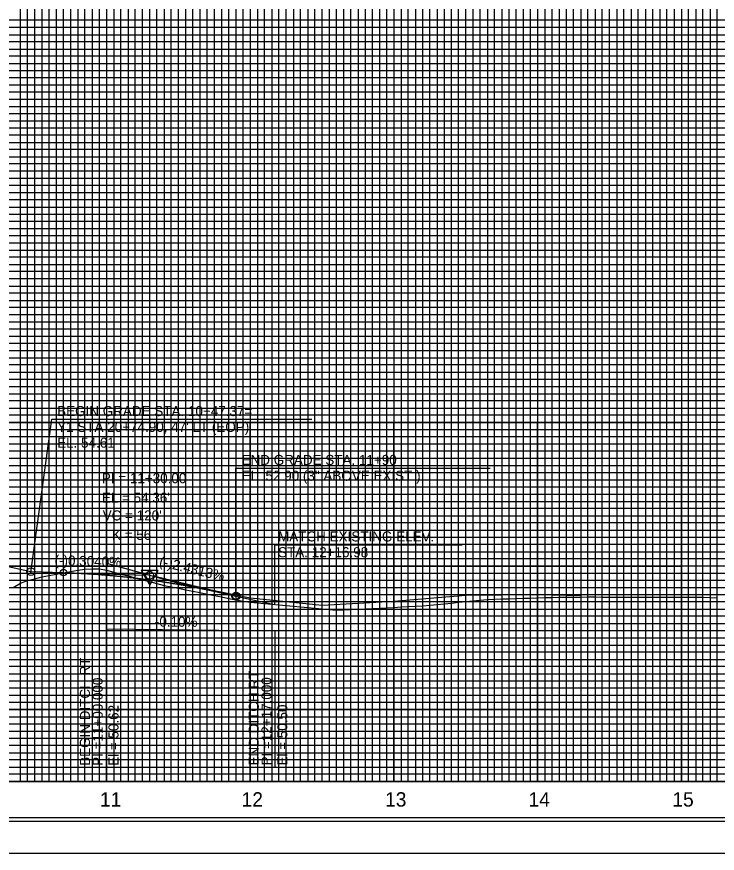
# Model space of a CAD drawing. Extents: x 2345490 to 2445302, y 465165 to 573888.
# Drawn here: x 2381804 to 2382292, y 532361 to 532944 of the extents above; entities that cross this region are included whole.
import ezdxf

# ---------------------------------------------------------------- set-up
doc = ezdxf.new("R2010")
doc.units = 0
for name, color, linetype in [('Old_Level_1', 7, 'Continuous'), ('Old_Level_18', 7, 'Continuous'), ('Old_Level_2', 7, 'Continuous'), ('Old_Level_3', 7, 'Continuous'), ('Old_Level_41', 7, 'Continuous'), ('Old_Level_42', 7, 'Continuous'), ('Old_Level_43', 7, 'Continuous'), ('Old_Level_50', 7, 'Continuous'), ('Old_Level_51', 7, 'Continuous'), ('Old_Level_57', 7, 'Continuous'), ('Old_Level_62', 7, 'Continuous'), ('Old_Level_63', 7, 'Continuous')]:
    doc.layers.add(name, color=color, linetype=linetype)

msp = doc.modelspace()

# ---------------------------------------------------------------- linework, layer by layer
at = {"layer": 'Old_Level_1'}
for points in [[(2381801.799, 532546.145), (2381806.799, 532549.13275), (2381811.799, 532550.8695), (2381816.799, 532552.128), (2381821.799, 532553.4715), (2381826.799, 532554.3915), (2381831.799, 532555.2835), (2381836.799, 532556.27575), (2381841.799, 532557.2585), (2381846.799, 532558.14025), (2381851.799, 532558.90725), (2381856.799, 532559.102), (2381861.799, 532559.02975), (2381866.799, 532558.10175), (2381871.799, 532556.787), (2381876.799, 532555.472), (2381881.799, 532554.15725), (2381886.799, 532552.84225), (2381891.799, 532551.5275), (2381896.799, 532550.2095), (2381901.799, 532548.89425), (2381906.799, 532547.6065), (2381911.799, 532546.603), (2381916.799, 532545.59575), (2381921.799, 532544.58425), (2381926.799, 532543.57275), (2381931.799, 532542.5615), (2381936.799, 532541.56275), (2381941.799, 532540.554), (2381946.799, 532539.54525), (2381951.799, 532538.5365), (2381956.799, 532537.528), (2381961.799, 532536.51925), (2381966.799, 532535.87925), (2381971.799, 532535.4215), (2381976.799, 532534.964), (2381981.799, 532534.5065), (2381986.799, 532534.04875), (2381991.799, 532533.59125), (2381996.799, 532533.121), (2382001.799, 532532.6625), (2382006.799, 532532.20425), (2382011.799, 532531.74575), (2382016.799, 532531.28725), (2382021.799, 532530.82875), (2382026.799, 532530.425), (2382031.799, 532530.49175), (2382036.799, 532530.76025), (2382041.799, 532531.0285), (2382046.799, 532531.29675), (2382051.799, 532531.56525), (2382056.799, 532531.8335), (2382061.799, 532532.00825), (2382066.799, 532532.2765), (2382071.799, 532532.54475), (2382076.799, 532532.81325), (2382081.799, 532533.0815), (2382086.799, 532533.35), (2382091.799, 532533.7715), (2382096.799, 532534.27475), (2382101.799, 532534.778), (2382106.799, 532535.28125), (2382111.799, 532535.78425), (2382116.799, 532536.2875), (2382121.799, 532536.79075), (2382126.799, 532537.294), (2382131.799, 532537.76775), (2382136.799, 532537.97175), (2382141.799, 532538.1305), (2382146.799, 532538.28925), (2382151.799, 532538.448), (2382156.799, 532538.61975), (2382161.799, 532538.778), (2382166.799, 532538.93525), (2382171.799, 532539.089), (2382176.799, 532539.2225), (2382181.799, 532539.289), (2382186.799, 532539.35175), (2382191.799, 532539.41125), (2382196.799, 532539.467), (2382201.799, 532539.50625), (2382206.799, 532539.50325), (2382211.799, 532539.495), (2382216.799, 532539.48275), (2382221.799, 532539.467), (2382226.799, 532539.44825), (2382231.799, 532539.45125), (2382236.799, 532539.46675), (2382241.799, 532539.47825), (2382246.799, 532539.48625), (2382251.799, 532539.4905), (2382256.799, 532539.415), (2382261.799, 532539.396), (2382266.799, 532539.393)], [(2382266.799, 532539.393), (2382271.799, 532539.3855), (2382276.799, 532539.37325), (2382281.799, 532539.31625), (2382286.799, 532539.1095), (2382291.799, 532538.9875)]]:
    msp.add_lwpolyline(points, dxfattribs=at)
at = {"layer": 'Old_Level_18'}
msp.add_lwpolyline([(2383216.79875, 533436.04975), (2381716.79875, 533436.04975), (2381716.79875, 532386.04975), (2383216.79875, 532386.04975)], close=True, dxfattribs=at)
at = {"layer": 'Old_Level_2'}
for p, q in [((2381791.799, 532562.18325), (2381814.16925, 532557.15)), ((2381814.16925, 532557.15), (2381836.799, 532556.46225)), ((2381836.799, 532556.46225), (2381894.0505, 532554.72175)), ((2381956.799, 532540.05), (2381899.47125, 532553.9885)), ((2381956.799, 532540.05), (2381983.779, 532534.35025))]:
    msp.add_line(p, q, dxfattribs=at)
msp.add_lwpolyline([(2381902.72475, 532557.9225), (2381890.98225, 532557.908), (2381896.86575, 532547.78975)], close=True, dxfattribs=at)
for centre, radius in [((2381814.16925, 532557.15), 2.75), ((2381836.799, 532556.46225), 2.25), ((2381896.799, 532554.638), 2.75), ((2381896.799, 532554.638), 2.75), ((2381956.799, 532540.05), 2.75), ((2381956.799, 532540.05), 2.25)]:
    msp.add_circle(centre, radius, dxfattribs=at)
msp.add_spline([(2381836.799, 532556.46225), (2381839.199, 532556.384), (2381841.599, 532556.29575), (2381843.999, 532556.19725), (2381846.399, 532556.0885), (2381848.799, 532555.96975), (2381851.199, 532555.8405), (2381853.599, 532555.70125), (2381855.999, 532555.55175), (2381858.399, 532555.392), (2381860.799, 532555.222), (2381863.199, 532555.04175), (2381865.599, 532554.8515), (2381867.999, 532554.65075), (2381870.399, 532554.44), (2381872.799, 532554.219), (2381875.199, 532553.98775), (2381877.599, 532553.74625), (2381879.999, 532553.49475), (2381882.399, 532553.23275), (2381884.799, 532552.96075), (2381887.199, 532552.6785), (2381889.599, 532552.386), (2381891.999, 532552.08325), (2381894.399, 532551.77025), (2381896.799, 532551.447), (2381899.199, 532551.11375), (2381901.599, 532550.77025), (2381903.999, 532550.4165), (2381906.399, 532550.0525), (2381908.799, 532549.67825), (2381911.199, 532549.29375), (2381913.599, 532548.89925), (2381915.999, 532548.4945), (2381918.399, 532548.0795), (2381920.799, 532547.65425), (2381923.199, 532547.21875), (2381925.599, 532546.773), (2381927.999, 532546.31725), (2381930.399, 532545.851), (2381932.799, 532545.37475), (2381935.199, 532544.88825), (2381937.599, 532544.3915), (2381939.999, 532543.8845), (2381942.399, 532543.3675), (2381944.799, 532542.84), (2381947.199, 532542.3025), (2381949.599, 532541.75475), (2381951.999, 532541.19675), (2381954.399, 532540.6285), (2381956.799, 532540.05)], degree=3, dxfattribs=at)
at = {"layer": 'Old_Level_3'}
for p, q in [((2381814.03875, 532556.54975), (2381828.82525, 532663.237)), ((2381828.82525, 532663.237), (2382009.71375, 532663.237)), ((2381956.799, 532540.05), (2381956.799, 532629.18325)), ((2381956.799, 532629.18325), (2382133.76675, 532629.18325)), ((2381983.77875, 532575.91425), (2381983.77875, 532534.35025)), ((2381983.77875, 532575.91425), (2382114.25025, 532575.91425)), ((2381866.799, 532517.25), (2381983.799, 532516.05)), ((2381866.799, 532517.25), (2381866.799, 532420.84507)), ((2381983.799, 532516.05), (2381983.799, 532420.84507))]:
    msp.add_line(p, q, dxfattribs=at)
at = {"layer": 'Old_Level_41'}
msp.add_line((2383216.79875, 532411.04975), (2381716.79875, 532411.04975), dxfattribs=at)
for points in [[(2381716.79875, 533436.04975), (2381766.79875, 533436.04975), (2381766.79875, 532411.04975), (2381816.79875, 532411.04975), (2381816.79875, 533436.04975), (2381866.79875, 533436.04975), (2381866.79875, 532411.04975), (2381916.79875, 532411.04975), (2381916.79875, 533436.04975), (2381966.79875, 533436.04975), (2381966.79875, 532411.04975), (2382016.79875, 532411.04975), (2382016.79875, 533436.04975), (2382066.79875, 533436.04975), (2382066.79875, 532411.04975), (2382116.79875, 532411.04975), (2382116.79875, 533436.04975), (2382166.79875, 533436.04975), (2382166.79875, 532411.04975), (2382216.79875, 532411.04975), (2382216.79875, 533436.04975), (2382266.79875, 533436.04975), (2382266.79875, 532411.04975), (2382316.79875, 532411.04975)], [(2381791.79875, 532411.04975), (2381791.79875, 533436.04975), (2381841.79875, 533436.04975), (2381841.79875, 532411.04975), (2381891.79875, 532411.04975), (2381891.79875, 533436.04975), (2381941.79875, 533436.04975), (2381941.79875, 532411.04975), (2381991.79875, 532411.04975), (2381991.79875, 533436.04975), (2382041.79875, 533436.04975), (2382041.79875, 532411.04975), (2382091.79875, 532411.04975), (2382091.79875, 533436.04975), (2382141.79875, 533436.04975), (2382141.79875, 532411.04975), (2382191.79875, 532411.04975), (2382191.79875, 533436.04975), (2382241.79875, 533436.04975), (2382241.79875, 532411.04975), (2382291.79875, 532411.04975), (2382291.79875, 533436.04975), (2382341.79875, 533436.04975)], [(2383216.79875, 532936.04975), (2381716.79875, 532936.04975), (2381716.79875, 532886.04975), (2383216.79875, 532886.04975)], [(2383216.79875, 532836.04975), (2381716.79875, 532836.04975), (2381716.79875, 532786.04975), (2383216.79875, 532786.04975)], [(2383216.79875, 532761.04975), (2381716.79875, 532761.04975), (2381716.79875, 532811.04975), (2383216.79875, 532811.04975)], [(2383216.79875, 532736.04975), (2381716.79875, 532736.04975), (2381716.79875, 532686.04975), (2383216.79875, 532686.04975)], [(2383216.79875, 532661.04975), (2381716.79875, 532661.04975), (2381716.79875, 532711.04975), (2383216.79875, 532711.04975)], [(2383216.79875, 532636.04975), (2381716.79875, 532636.04975), (2381716.79875, 532586.04975), (2383216.79875, 532586.04975)], [(2383216.79875, 532536.04975), (2381716.79875, 532536.04975), (2381716.79875, 532486.04975), (2383216.79875, 532486.04975)], [(2383216.79875, 532461.04975), (2381716.79875, 532461.04975), (2381716.79875, 532511.04975), (2383216.79875, 532511.04975)], [(2383216.79875, 532436.04975), (2381716.79875, 532436.04975)]]:
    msp.add_lwpolyline(points, dxfattribs=at)
at = {"layer": 'Old_Level_42'}
for points in [[(2383216.79875, 532861.04975), (2381716.79875, 532861.04975), (2381716.79875, 532911.04975), (2383216.79875, 532911.04975)], [(2383216.79875, 532561.04975), (2381716.79875, 532561.04975), (2381716.79875, 532611.04975), (2383216.79875, 532611.04975)]]:
    msp.add_lwpolyline(points, dxfattribs=at)
at = {"layer": 'Old_Level_43'}
for points in [[(2381806.79875, 533436.04975), (2381806.79875, 532411.04975), (2381811.79875, 532411.04975), (2381811.79875, 533436.04975)], [(2381821.79875, 533436.04975), (2381821.79875, 532411.04975), (2381826.79875, 532411.04975), (2381826.79875, 533436.04975)], [(2381831.79875, 533436.04975), (2381831.79875, 532411.04975), (2381836.79875, 532411.04975), (2381836.79875, 533436.04975)], [(2381846.79875, 533436.04975), (2381846.79875, 532411.04975), (2381851.79875, 532411.04975), (2381851.79875, 533436.04975)], [(2381856.79875, 533436.04975), (2381856.79875, 532411.04975), (2381861.79875, 532411.04975), (2381861.79875, 533436.04975)], [(2381871.79875, 533436.04975), (2381871.79875, 532411.04975), (2381876.79875, 532411.04975), (2381876.79875, 533436.04975)], [(2381881.79875, 533436.04975), (2381881.79875, 532411.04975), (2381886.79875, 532411.04975), (2381886.79875, 533436.04975)], [(2381896.79875, 533436.04975), (2381896.79875, 532411.04975), (2381901.79875, 532411.04975), (2381901.79875, 533436.04975)], [(2381906.79875, 533436.04975), (2381906.79875, 532411.04975), (2381911.79875, 532411.04975), (2381911.79875, 533436.04975)], [(2381921.79875, 533436.04975), (2381921.79875, 532411.04975), (2381926.79875, 532411.04975), (2381926.79875, 533436.04975)], [(2381931.79875, 532411.04975), (2381936.79875, 532411.04975), (2381936.79875, 533436.04975)], [(2381931.79875, 533436.04975), (2381931.79875, 532411.04975)], [(2381946.79875, 533436.04975), (2381946.79875, 532411.04975), (2381951.79875, 532411.04975), (2381951.79875, 533436.04975)], [(2381956.79875, 533436.04975), (2381956.79875, 532411.04975), (2381961.79875, 532411.04975), (2381961.79875, 533436.04975)], [(2381971.79875, 533436.04975), (2381971.79875, 532411.04975), (2381976.79875, 532411.04975), (2381976.79875, 533436.04975)], [(2381981.79875, 533436.04975), (2381981.79875, 532411.04975), (2381986.79875, 532411.04975), (2381986.79875, 533436.04975)], [(2381996.79875, 533436.04975), (2381996.79875, 532411.04975), (2382001.79875, 532411.04975), (2382001.79875, 533436.04975)], [(2382006.79875, 533436.04975), (2382006.79875, 532411.04975), (2382011.79875, 532411.04975), (2382011.79875, 533436.04975)], [(2382021.79875, 533436.04975), (2382021.79875, 532411.04975), (2382026.79875, 532411.04975), (2382026.79875, 533436.04975)], [(2382031.79875, 533436.04975), (2382031.79875, 532411.04975), (2382036.79875, 532411.04975), (2382036.79875, 533436.04975)], [(2382046.79875, 533436.04975), (2382046.79875, 532411.04975), (2382051.79875, 532411.04975), (2382051.79875, 533436.04975)], [(2382056.79875, 533436.04975), (2382056.79875, 532411.04975), (2382061.79875, 532411.04975), (2382061.79875, 533436.04975)], [(2382071.79875, 533436.04975), (2382071.79875, 532411.04975), (2382076.79875, 532411.04975), (2382076.79875, 533436.04975)], [(2382081.79875, 533436.04975), (2382081.79875, 532411.04975), (2382086.79875, 532411.04975), (2382086.79875, 533436.04975)], [(2382096.79875, 533436.04975), (2382096.79875, 532411.04975), (2382111.79875, 532411.04975), (2382111.79875, 533436.04975)], [(2382101.79875, 533436.04975), (2382101.79875, 532411.04975), (2382106.79875, 532411.04975), (2382106.79875, 533436.04975)], [(2382121.79875, 533436.04975), (2382121.79875, 532411.04975), (2382126.79875, 532411.04975), (2382126.79875, 533436.04975)], [(2382131.79875, 533436.04975), (2382131.79875, 532411.04975), (2382136.79875, 532411.04975), (2382136.79875, 533436.04975)], [(2382146.79875, 533436.04975), (2382146.79875, 532411.04975), (2382151.79875, 532411.04975), (2382151.79875, 533436.04975)], [(2382156.79875, 533436.04975), (2382156.79875, 532411.04975), (2382161.79875, 532411.04975), (2382161.79875, 533436.04975)], [(2382171.79875, 533436.04975), (2382171.79875, 532411.04975), (2382176.79875, 532411.04975), (2382176.79875, 533436.04975)], [(2382181.79875, 533436.04975), (2382181.79875, 532411.04975), (2382186.79875, 532411.04975), (2382186.79875, 533436.04975)], [(2382196.79875, 533436.04975), (2382196.79875, 532411.04975), (2382201.79875, 532411.04975), (2382201.79875, 533436.04975)], [(2382206.79875, 533436.04975), (2382206.79875, 532411.04975), (2382211.79875, 532411.04975), (2382211.79875, 533436.04975)], [(2382221.79875, 533436.04975), (2382221.79875, 532411.04975), (2382226.79875, 532411.04975), (2382226.79875, 533436.04975)], [(2382231.79875, 533436.04975), (2382231.79875, 532411.04975), (2382236.79875, 532411.04975), (2382236.79875, 533436.04975)], [(2382246.79875, 533436.04975), (2382246.79875, 532411.04975)], [(2382251.79875, 533436.04975), (2382251.79875, 532411.04975), (2382256.79875, 532411.04975), (2382256.79875, 533436.04975), (2382261.79875, 533436.04975), (2382261.79875, 532411.04975), (2382271.79875, 532411.04975), (2382271.79875, 533436.04975), (2382276.79875, 533436.04975), (2382276.79875, 532411.04975), (2382281.79875, 532411.04975), (2382281.79875, 533436.04975), (2382286.79875, 533436.04975), (2382286.79875, 532411.04975)], [(2382101.79875, 533435.44975), (2382101.79875, 532411.04975), (2382106.79875, 532411.04975), (2382106.79875, 533435.44975)], [(2383166.79875, 532941.04975), (2381766.79875, 532941.04975), (2381766.79875, 532931.04975), (2383166.79875, 532931.04975)], [(2383166.79875, 532926.04975), (2381766.79875, 532926.04975), (2381766.79875, 532921.04975), (2383166.79875, 532921.04975)], [(2383166.79875, 532916.04975), (2381766.79875, 532916.04975)], [(2381766.79875, 532906.04975), (2383166.79875, 532906.04975)], [(2383166.79875, 532901.04975), (2381766.79875, 532901.04975), (2381766.79875, 532896.04975), (2383166.79875, 532896.04975)], [(2383166.79875, 532891.04975), (2381766.79875, 532891.04975), (2381766.79875, 532881.04975), (2383166.79875, 532881.04975)], [(2383166.79875, 532876.04975), (2381766.79875, 532876.04975), (2381766.79875, 532871.04975), (2383166.79875, 532871.04975)], [(2383166.79875, 532866.04975), (2381766.79875, 532866.04975), (2381766.79875, 532856.04975), (2383166.79875, 532856.04975)], [(2383166.79875, 532851.04975), (2381766.79875, 532851.04975), (2381766.79875, 532846.04975), (2383166.79875, 532846.04975)], [(2383166.79875, 532841.04975), (2381766.79875, 532841.04975), (2381766.79875, 532831.04975), (2383166.79875, 532831.04975)], [(2383166.79875, 532826.04975), (2381766.79875, 532826.04975), (2381766.79875, 532821.04975), (2383166.79875, 532821.04975)], [(2383166.79875, 532816.04975), (2381766.79875, 532816.04975), (2381766.79875, 532806.04975), (2383166.79875, 532806.04975)], [(2383166.79875, 532801.04975), (2381766.79875, 532801.04975), (2381766.79875, 532796.04975), (2383166.79875, 532796.04975)], [(2383166.79875, 532791.04975), (2381766.79875, 532791.04975), (2381766.79875, 532781.04975), (2383166.79875, 532781.04975)], [(2383166.79875, 532776.04975), (2381766.79875, 532776.04975), (2381766.79875, 532771.04975), (2383166.79875, 532771.04975)], [(2383166.79875, 532766.04975), (2381766.79875, 532766.04975), (2381766.79875, 532756.04975), (2383166.79875, 532756.04975)], [(2383166.79875, 532751.04975), (2381766.79875, 532751.04975), (2381766.79875, 532746.04975), (2383166.79875, 532746.04975)], [(2383166.79875, 532741.04975), (2381766.79875, 532741.04975), (2381766.79875, 532731.04975), (2383166.79875, 532731.04975)], [(2383166.79875, 532726.04975), (2381766.79875, 532726.04975), (2381766.79875, 532721.04975), (2383166.79875, 532721.04975)], [(2383166.79875, 532716.04975), (2381766.79875, 532716.04975), (2381766.79875, 532706.04975), (2383166.79875, 532706.04975)], [(2383166.79875, 532701.04975), (2381766.79875, 532701.04975), (2381766.79875, 532696.04975), (2383166.79875, 532696.04975)], [(2383166.79875, 532691.04975), (2381766.79875, 532691.04975), (2381766.79875, 532681.04975), (2383166.79875, 532681.04975)], [(2383166.79875, 532676.04975), (2381766.79875, 532676.04975), (2381766.79875, 532671.04975), (2383166.79875, 532671.04975)], [(2383166.79875, 532666.04975), (2381766.79875, 532666.04975), (2381766.79875, 532656.04975), (2383166.79875, 532656.04975)], [(2383166.79875, 532651.04975), (2381766.79875, 532651.04975), (2381766.79875, 532646.04975), (2383166.79875, 532646.04975)], [(2383166.79875, 532641.04975), (2381766.79875, 532641.04975), (2381766.79875, 532631.04975), (2383166.79875, 532631.04975)], [(2383166.79875, 532626.04975), (2381766.79875, 532626.04975), (2381766.79875, 532621.04975), (2383166.79875, 532621.04975)], [(2383166.79875, 532616.04975), (2381766.79875, 532616.04975)], [(2381766.79875, 532606.04975), (2383166.79875, 532606.04975)], [(2383166.79875, 532601.04975), (2381766.79875, 532601.04975), (2381766.79875, 532596.04975), (2383166.79875, 532596.04975)], [(2383166.79875, 532591.04975), (2381766.79875, 532591.04975)], [(2381766.79875, 532581.04975), (2383166.79875, 532581.04975)], [(2383166.79875, 532576.04975), (2381766.79875, 532576.04975), (2381766.79875, 532571.04975), (2383166.79875, 532571.04975)], [(2383166.79875, 532566.04975), (2381766.79875, 532566.04975), (2381766.79875, 532556.04975), (2383166.79875, 532556.04975)], [(2383166.79875, 532551.04975), (2381766.79875, 532551.04975), (2381766.79875, 532546.04975), (2383166.79875, 532546.04975)], [(2383166.79875, 532541.04975), (2381766.79875, 532541.04975), (2381766.79875, 532531.04975), (2383166.79875, 532531.04975)], [(2383166.79875, 532526.04975), (2381766.79875, 532526.04975), (2381766.79875, 532521.04975), (2383166.79875, 532521.04975)], [(2383166.79875, 532516.04975), (2381766.79875, 532516.04975), (2381766.79875, 532506.04975), (2383166.79875, 532506.04975)], [(2383166.79875, 532501.04975), (2381766.79875, 532501.04975), (2381766.79875, 532496.04975), (2383166.79875, 532496.04975)], [(2383166.79875, 532491.04975), (2381766.79875, 532491.04975), (2381766.79875, 532481.04975), (2383166.79875, 532481.04975)], [(2383166.79875, 532476.04975), (2381766.79875, 532476.04975), (2381766.79875, 532471.04975), (2383166.79875, 532471.04975)], [(2383166.79875, 532466.04975), (2381766.79875, 532466.04975), (2381766.79875, 532456.04975), (2383166.79875, 532456.04975)], [(2383166.79875, 532451.04975), (2381766.79875, 532451.04975), (2381766.79875, 532446.04975), (2383166.79875, 532446.04975)], [(2383166.79875, 532441.04975), (2381766.79875, 532441.04975), (2381766.79875, 532431.04975), (2383166.79875, 532431.04975)], [(2383166.79875, 532426.04975), (2381766.79875, 532426.04975), (2381766.79875, 532421.04975), (2383166.79875, 532421.04975)], [(2383166.79875, 532416.04975), (2381766.79875, 532416.04975)]]:
    msp.add_lwpolyline(points, dxfattribs=at)
at = {"layer": 'Old_Level_50'}
msp.add_lwpolyline([(2383229.29875, 533438.59975), (2381562.79875, 533438.59975), (2381562.79875, 532383.49975), (2383229.29875, 532383.49975)], close=True, dxfattribs=at)
at = {"layer": 'Old_Level_51'}
msp.add_lwpolyline([(2383233.79875, 533461.04975), (2381549.79875, 533461.04975), (2381549.79875, 532361.04975), (2383233.79875, 532361.04975)], close=True, dxfattribs=at)
at = {"layer": 'Old_Level_57'}
for p, q in [((2381716.79925, 532661.05025), (2382266.79875, 532661.05025)), ((2381866.79875, 532411.05025), (2381866.79875, 532661.05025)), ((2381966.79875, 532411.05025), (2381966.79875, 532661.05025)), ((2382066.79875, 532411.05025), (2382066.79875, 532661.05025)), ((2382166.79875, 532411.05025), (2382166.79875, 532661.05025)), ((2382266.79875, 532411.05025), (2382266.79875, 532661.05025)), ((2381716.79925, 532611.05025), (2382266.79875, 532611.05025)), ((2381716.79925, 532561.05025), (2382266.79875, 532561.05025)), ((2381716.79925, 532511.05025), (2382266.79875, 532511.05025)), ((2381716.799, 532461.05025), (2382266.79875, 532461.05025)), ((2381716.79925, 532411.05025), (2382266.79875, 532411.05025))]:
    msp.add_line(p, q, dxfattribs=at)
at = {"layer": 'Old_Level_63'}
msp.add_line((2381766.79875, 532411.04975), (2382198.83425, 532411.04975), dxfattribs=at)
msp.add_lwpolyline([(2381866.799, 532563.05), (2381916.799, 532549.05), (2381966.799, 532538.95), (2382016.799, 532533.85), (2382066.799, 532536.65), (2382116.799, 532540.85), (2382166.799, 532541.35), (2382196.799, 532540.55)], dxfattribs=at)

# ---------------------------------------------------------------- texts
at = {"layer": 'Old_Level_2'}
for s, height, p in [('BEGIN GRADE STA. 10+47.37=', 7.0000005, (2381832.41675, 532665.46)), ("Y1 STA 20+74.90, 47' LT (EOP)", 7.0000005, (2381832.41675, 532654.46)), ('EL. 54.61', 7.000001, (2381832.41675, 532643.46)), ('END GRADE STA. 11+90', 7.0000005, (2381960.788, 532631.4475)), ('EL. 52.90 (3" ABOVE EXIST.)', 7.0000005, (2381960.788, 532620.4475)), ('PI = 11+30.00', 7.0000005, (2381863.519, 532618.7195)), ("EL = 54.36'", 7.0000005, (2381863.5195, 532605.171)), ("VC = 120'", 7.000001, (2381864.124, 532592.79775)), ('K = 56', 7.000001, (2381870.573, 532579.2735)), ('MATCH EXISTING ELEV.', 7.0000005, (2381986.16675, 532578.17825)), ('STA. 12+16.98', 7.0000005, (2381986.16675, 532567.17825))]:
    msp.add_text(s, height=height, dxfattribs=at).set_placement(p)
for s, rotation, p in [('(-)0.3040%', 358.25869167, (2381830.54325, 532561.69675)), ('(-)2.4313%', 346.33466389, (2381902.9915, 532561.28375))]:
    msp.add_text(s, height=7.000001, rotation=rotation, dxfattribs=at).set_placement(p)
at = {"layer": 'Old_Level_3'}
for s, height, rotation, p in [('-0.10%', 7, 359.4124, (2381900.3665, 532518.971)), ('BEGIN DITCH RT', 7.0000005, 90, (2381855.24905, 532421.93915)), ('END DITCH RT', 7.0000005, 90, (2381972.75967, 532422.18661)), ('PI =11+00.000', 7.0000005, 90, (2381864.12295, 532421.93915)), ('PI =12+17.000', 7.0000005, 90, (2381981.63358, 532422.18661)), ('El = 50.62', 7.000001, 90, (2381875.12295, 532421.93915)), ('El = 50.50', 7.000001, 90, (2381992.63358, 532422.18661))]:
    msp.add_text(s, height=height, rotation=rotation, dxfattribs=at).set_placement(p)
at = {"layer": 'Old_Level_62'}
for s, p in [('11', (2381862.222, 532393.55)), ('12', (2381960.77025, 532393.55)), ('13', (2382060.605, 532393.55)), ('14', (2382160.4475, 532393.55)), ('15', (2382260.54, 532393.55))]:
    msp.add_text(s, height=10.000001, dxfattribs=at).set_placement(p)

doc.saveas('drawing.dxf')
